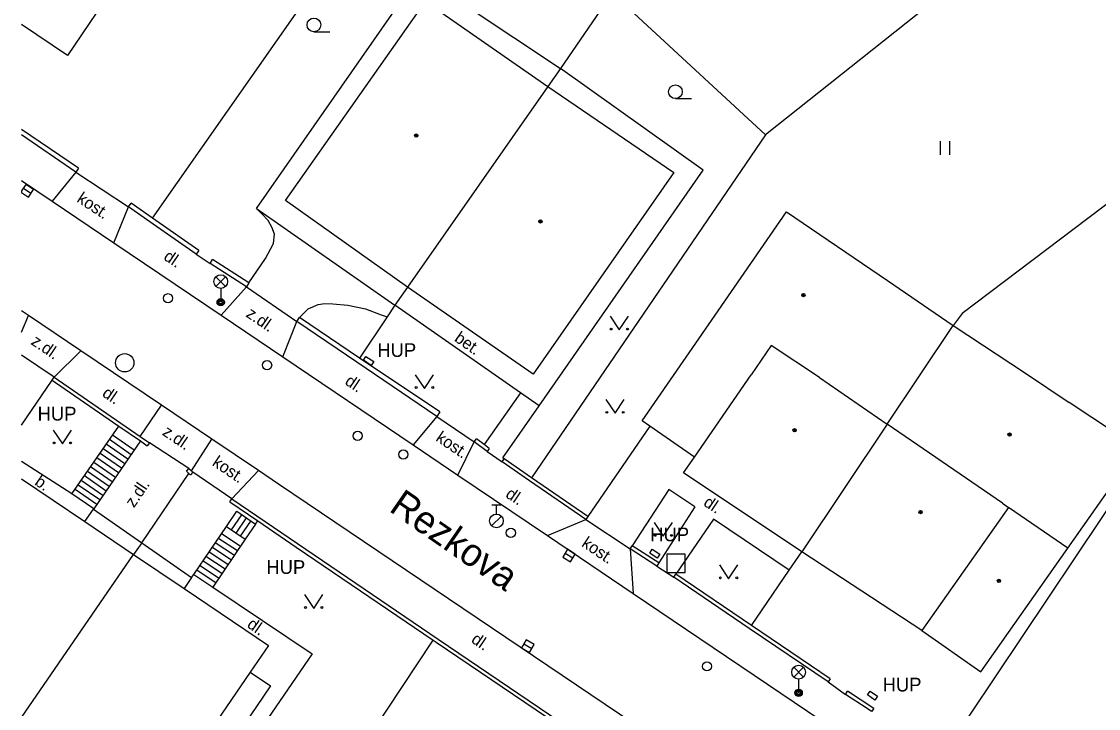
# Model space of a CAD drawing. Extents: x -600391 to -599491, y -1160176 to -1159402.
# Drawn here: x -600391 to -600332.3, y -1160041.1 to -1160003.6 of the extents above; entities that cross this region are included whole.
import ezdxf

# ---------------------------------------------------------------- set-up
doc = ezdxf.new("R2010")
doc.units = 0
for name, color, linetype in [('Level 10', 7, 'Continuous'), ('Level 11', 7, 'Continuous'), ('Level 24', 7, 'Continuous'), ('Level 26', 7, 'Continuous'), ('Level 27', 7, 'Continuous'), ('Level 28', 7, 'Continuous'), ('Level 33', 7, 'Continuous'), ('Level 36', 7, 'Continuous'), ('Level 39', 7, 'Continuous'), ('Level 40', 7, 'Continuous'), ('Level 41', 7, 'Continuous'), ('Level 49', 7, 'Continuous'), ('Level 5', 7, 'Continuous'), ('Level 7', 7, 'Continuous'), ('Level 8', 7, 'Continuous'), ('Vrstva 27', 7, 'Continuous')]:
    doc.layers.add(name, color=color, linetype=linetype)

msp = doc.modelspace()

# ---------------------------------------------------------------- linework, layer by layer
at = {"layer": 'Level 10'}
for points in [[(-600391.008, -1160012.297), (-600389.33, -1160013.43), (-600385.97, -1160015.7), (-600380.12, -1160019.65), (-600376.77, -1160021.91), (-600369.66, -1160026.71), (-600367.22, -1160028.36), (-600362.33, -1160031.66), (-600357.66, -1160034.81), (-600345.98, -1160042.7), (-600342.95, -1160044.75), (-600341.58, -1160045.67), (-600338.1, -1160048.02), (-600335.29, -1160049.92), (-600325.8, -1160056.33), (-600315.13, -1160063.54), (-600309.38, -1160067.42), (-600304.6, -1160070.65), (-600301.7, -1160072.61), (-600258.67, -1160101.64)], [(-600376.99, -1160028.86), (-600378.09, -1160028.12), (-600380.63, -1160026.4), (-600383.37, -1160024.55), (-600387.77, -1160021.58), (-600390.62, -1160019.66), (-600391.008, -1160019.398)], [(-600286.14, -1160090.13), (-600298.33, -1160081.92), (-600327.82, -1160062.03), (-600331.39, -1160059.62), (-600334.69, -1160057.39), (-600338.31, -1160054.95), (-600376.99, -1160028.86)]]:
    msp.add_lwpolyline(points, dxfattribs=at)
at = {"layer": 'Level 11'}
for p, q in [((-600391.008, -1160020.577), (-600390.62, -1160019.66)), ((-600388.26, -1160029.39), (-600391.008, -1160027.625))]:
    msp.add_line(p, q, dxfattribs=at)
for points in [[(-600378.19, -1160013.82), (-600369.31, -1160001.07)], [(-600369.31, -1160001.07), (-600361.63, -1160006.19)], [(-600353.85, -1160011.73), (-600361.63, -1160006.19)], [(-600388.05, -1160011.84), (-600389.33, -1160013.43)], [(-600362.79, -1160024.58), (-600353.85, -1160011.73)], [(-600385.97, -1160015.7), (-600385.18, -1160013.73)], [(-600378.61, -1160017.88), (-600377.7, -1160016.55), (-600377.27, -1160015.74), (-600377.21, -1160015.23), (-600377.36, -1160014.85), (-600377.56, -1160014.48), (-600377.9, -1160014.12), (-600378.19, -1160013.82)], [(-600378.19, -1160013.82), (-600370.65, -1160019.1)], [(-600378.74, -1160018.09), (-600380.12, -1160019.65)], [(-600375.86, -1160019.77), (-600375.39, -1160019.29), (-600374.84, -1160019.07), (-600374.47, -1160019.01), (-600374.03, -1160019.03), (-600373.22, -1160019.1), (-600372.26, -1160019.3), (-600371.41, -1160019.62), (-600371.08, -1160019.74)], [(-600362.79, -1160024.58), (-600363.81, -1160023.87), (-600370.65, -1160019.1)], [(-600376.77, -1160021.91), (-600376, -1160019.98)], [(-600387.77, -1160021.58), (-600389.23, -1160023.03)], [(-600363.81, -1160023.87), (-600365.79, -1160026.7)], [(-600384.54, -1160026.25), (-600383.37, -1160024.55)], [(-600364.7, -1160027.48), (-600364.77, -1160027.43), (-600362.79, -1160024.58)], [(-600368.37, -1160025.16), (-600369.66, -1160026.71)], [(-600384.52, -1160026.5), (-600387.07, -1160030.21), (-600388.26, -1160029.39), (-600385.71, -1160025.69)], [(-600356.75, -1160025.7), (-600360.13, -1160030.62)], [(-600384.87, -1160027), (-600386.05, -1160026.19)], [(-600385.38, -1160027.74), (-600386.56, -1160026.93)], [(-600385.21, -1160027.5), (-600386.39, -1160026.68)], [(-600385.04, -1160027.25), (-600386.22, -1160026.43)], [(-600381.75, -1160028.13), (-600380.63, -1160026.4)], [(-600367.22, -1160028.36), (-600366.33, -1160026.54)], [(-600385.72, -1160028.24), (-600386.9, -1160027.42)], [(-600385.55, -1160027.99), (-600386.73, -1160027.18)], [(-600386.06, -1160028.73), (-600387.24, -1160027.92)], [(-600385.89, -1160028.49), (-600387.07, -1160027.67)], [(-600378.09, -1160028.12), (-600379.55, -1160029.65)], [(-600386.57, -1160029.47), (-600387.75, -1160028.66)], [(-600386.4, -1160029.23), (-600387.58, -1160028.41)], [(-600386.23, -1160028.98), (-600387.41, -1160028.16)], [(-600386.91, -1160029.97), (-600388.09, -1160029.15)], [(-600386.74, -1160029.72), (-600387.92, -1160028.91)], [(-600355.72, -1160029.15), (-600357.71, -1160032.22)], [(-600354.3, -1160030.1), (-600355.72, -1160029.15)], [(-600379.84, -1160031.17), (-600379.27, -1160030.33)], [(-600379.27, -1160030.33), (-600378.25, -1160031.04)], [(-600354.3, -1160030.1), (-600356.27, -1160033.15)], [(-600387.55, -1160030.9), (-600384.9, -1160032.69)], [(-600379.56, -1160031.35), (-600378.99, -1160030.53)], [(-600379.31, -1160031.52), (-600378.74, -1160030.7)], [(-600379.07, -1160031.69), (-600378.5, -1160030.87)], [(-600378.25, -1160031.04), (-600378.82, -1160031.86)], [(-600378.25, -1160031.04), (-600378.13, -1160030.86)], [(-600362.33, -1160031.66), (-600360.24, -1160030.78)], [(-600353.29, -1160030.77), (-600355.33, -1160033.76)], [(-600349.15, -1160033.54), (-600353.29, -1160030.77)], [(-600381.62, -1160033.78), (-600379.84, -1160031.17)], [(-600380.13, -1160031.53), (-600379.07, -1160032.24)], [(-600379.84, -1160031.17), (-600378.82, -1160031.86)], [(-600378.82, -1160031.86), (-600380.57, -1160034.48)], [(-600380.46, -1160032.03), (-600379.4, -1160032.73)], [(-600380.3, -1160031.78), (-600379.24, -1160032.48)], [(-600384.9, -1160032.69), (-600382.15, -1160034.55)], [(-600380.96, -1160032.78), (-600379.9, -1160033.48)], [(-600380.8, -1160032.53), (-600379.74, -1160033.23)], [(-600380.63, -1160032.28), (-600379.57, -1160032.98)], [(-600357.82, -1160032.39), (-600357.66, -1160034.81)], [(-600351.22, -1160036.56), (-600349.15, -1160033.54), (-600348.47, -1160032.55)], [(-600381.3, -1160033.27), (-600380.24, -1160033.98)], [(-600381.13, -1160033.02), (-600380.07, -1160033.73)], [(-600381.74, -1160033.95), (-600381.62, -1160033.78)], [(-600381.62, -1160033.78), (-600380.57, -1160034.48)], [(-600381.46, -1160033.52), (-600380.4, -1160034.23)], [(-600380.57, -1160034.48), (-600375.17, -1160038.1), (-600382.21, -1160048.4), (-600382.91, -1160047.96), (-600385.26, -1160051.34)], [(-600378.54, -1160039.1), (-600383.44, -1160046.26)]]:
    msp.add_lwpolyline(points, dxfattribs=at)
at = {"layer": 'Level 24'}
for points in [[(-600372.23, -1160021.89), (-600371.81, -1160022.17), (-600371.95, -1160022.38), (-600372.37, -1160022.1), (-600372.23, -1160021.89)], [(-600356.62, -1160032.4), (-600356.21, -1160032.68), (-600356.35, -1160032.89), (-600356.76, -1160032.61), (-600356.62, -1160032.4)], [(-600344.75, -1160040.15), (-600344.34, -1160040.42), (-600344.48, -1160040.63), (-600344.89, -1160040.35), (-600344.75, -1160040.15)]]:
    msp.add_lwpolyline(points, dxfattribs=at)
at = {"layer": 'Level 26'}
msp.add_lwpolyline([(-600355.83, -1160033.67), (-600354.83, -1160033.67), (-600354.83, -1160032.67), (-600355.83, -1160032.67)], close=True, dxfattribs=at)
at = {"layer": 'Level 27'}
for p, q in [((-600390.907, -1160012.72), (-600390.493, -1160013)), ((-600361.372, -1160032.618), (-600360.948, -1160032.882)), ((-600363.616, -1160037.564), (-600363.184, -1160037.816))]:
    msp.add_line(p, q, dxfattribs=at)
for points in [[(-600361.504, -1160032.83), (-600361.08, -1160033.094), (-600360.816, -1160032.67), (-600361.24, -1160032.406)], [(-600363.742, -1160037.78), (-600363.31, -1160038.032), (-600363.058, -1160037.6), (-600363.49, -1160037.348)]]:
    msp.add_lwpolyline(points, close=True, dxfattribs=at)
msp.add_circle((-600385.38, -1160022.24), 0.5, dxfattribs=at)
at = {"layer": 'Level 28'}
for p, q in [((-600365.37, -1160029.985), (-600364.87, -1160029.985)), ((-600365.12, -1160030.485), (-600365.12, -1160029.985)), ((-600365.378, -1160031.132), (-600364.848, -1160030.602))]:
    msp.add_line(p, q, dxfattribs=at)
for centre, radius in [((-600383.02, -1160018.72), 0.25), ((-600377.62, -1160022.37), 0.25), ((-600372.68, -1160026.22), 0.25), ((-600370.19, -1160027.24), 0.25), ((-600365.12, -1160030.86), 0.375), ((-600364.33, -1160031.51), 0.25), ((-600353.64, -1160038.79), 0.25)]:
    msp.add_circle(centre, radius, dxfattribs=at)
at = {"layer": 'Level 33'}
for p, q in [((-600380.415, -1160018.08), (-600379.885, -1160017.55)), ((-600380.415, -1160017.55), (-600379.885, -1160018.08)), ((-600380.15, -1160018.19), (-600380.15, -1160018.94)), ((-600348.905, -1160039.37), (-600348.375, -1160038.84)), ((-600348.905, -1160038.84), (-600348.375, -1160039.37)), ((-600348.64, -1160039.48), (-600348.64, -1160040.23))]:
    msp.add_line(p, q, dxfattribs=at)
for centre, radius in [((-600380.15, -1160017.815), 0.375), ((-600380.15, -1160018.94), 0.2), ((-600380.15, -1160018.94), 0.145), ((-600380.15, -1160018.94), 0.0876), ((-600348.64, -1160039.105), 0.375), ((-600348.64, -1160040.23), 0.2), ((-600348.64, -1160040.23), 0.145), ((-600348.64, -1160040.23), 0.0876)]:
    msp.add_circle(centre, radius, dxfattribs=at)
at = {"layer": 'Level 36'}
for p, q in [((-600375.07, -1160004.195), (-600374.195, -1160004.195)), ((-600355.36, -1160007.835), (-600354.485, -1160007.835)), ((-600340.904, -1160010.903), (-600340.904, -1160010.153)), ((-600340.404, -1160010.903), (-600340.404, -1160010.153))]:
    msp.add_line(p, q, dxfattribs=at)
for points in [[(-600358.92, -1160019.7), (-600358.42, -1160020.45), (-600357.92, -1160019.7)], [(-600369.54, -1160022.89), (-600369.04, -1160023.64), (-600368.54, -1160022.89)], [(-600359.15, -1160024.24), (-600358.65, -1160024.99), (-600358.15, -1160024.24)], [(-600389.28, -1160025.91), (-600388.78, -1160026.66), (-600388.28, -1160025.91)], [(-600356.52, -1160030.95), (-600356.02, -1160031.7), (-600355.52, -1160030.95)], [(-600352.96, -1160033.26), (-600352.46, -1160034.01), (-600351.96, -1160033.26)], [(-600375.58, -1160034.88), (-600375.08, -1160035.63), (-600374.58, -1160034.88)]]:
    msp.add_lwpolyline(points, dxfattribs=at)
for centre, radius in [((-600375.07, -1160003.82), 0.375), ((-600355.36, -1160007.46), 0.375), ((-600358.87, -1160020.4), 0.05), ((-600357.971, -1160020.4), 0.05), ((-600369.49, -1160023.59), 0.05), ((-600368.591, -1160023.59), 0.05), ((-600359.1, -1160024.94), 0.05), ((-600358.201, -1160024.94), 0.05), ((-600389.23, -1160026.61), 0.05), ((-600388.331, -1160026.61), 0.05), ((-600356.47, -1160031.65), 0.05), ((-600355.571, -1160031.65), 0.05), ((-600352.91, -1160033.96), 0.05), ((-600352.011, -1160033.96), 0.05), ((-600375.53, -1160035.58), 0.05), ((-600374.631, -1160035.58), 0.05)]:
    msp.add_circle(centre, radius, dxfattribs=at)
at = {"layer": 'Level 39'}
for centre, radius in [((-600369.49, -1160009.85), 0.09), ((-600369.49, -1160009.85), 0.0398), ((-600362.72, -1160014.53), 0.09), ((-600362.72, -1160014.53), 0.0398), ((-600348.38, -1160018.55), 0.09), ((-600348.38, -1160018.55), 0.0398), ((-600348.86, -1160025.92), 0.09), ((-600348.86, -1160025.92), 0.0398), ((-600337.14, -1160026.15), 0.09), ((-600337.14, -1160026.15), 0.0398), ((-600341.99, -1160030.38), 0.09), ((-600341.99, -1160030.38), 0.0398), ((-600337.72, -1160034.13), 0.09), ((-600337.72, -1160034.13), 0.0398)]:
    msp.add_circle(centre, radius, dxfattribs=at)
at = {"layer": 'Level 5'}
for p, q in [((-600388.51, -1160005.48), (-600391.008, -1160003.79)), ((-600391.008, -1160028.561), (-600387.55, -1160030.9)), ((-600391.008, -1160041.584), (-600384.9, -1160032.69))]:
    msp.add_line(p, q, dxfattribs=at)
for points in [[(-600381.83, -1159995.61), (-600388.51, -1160005.48)], [(-600376.61, -1160013.4), (-600368.98, -1160002.54)], [(-600368.98, -1160002.54), (-600362.32, -1160007.18)], [(-600362.32, -1160007.18), (-600369.96, -1160018.11)], [(-600362.32, -1160007.18), (-600355.45, -1160011.87)], [(-600355.45, -1160011.87), (-600363.11, -1160022.86)], [(-600369.96, -1160018.11), (-600376.61, -1160013.4)], [(-600354.08, -1160020.93), (-600349.3, -1160014.01)], [(-600349.3, -1160014.01), (-600343.8, -1160017.76)], [(-600363.11, -1160022.86), (-600369.96, -1160018.11)], [(-600343.8, -1160017.76), (-600340.22, -1160020.2)], [(-600343.81, -1160025.58), (-600340.22, -1160020.2)], [(-600340.22, -1160020.2), (-600336.28, -1160022.81)], [(-600357.17, -1160025.41), (-600354.08, -1160020.93)], [(-600350.13, -1160021.3), (-600351.23, -1160022.9)], [(-600347.51, -1160023.04), (-600350.13, -1160021.3)], [(-600336.28, -1160022.81), (-600333.89, -1160024.4)], [(-600354.32, -1160027.38), (-600351.23, -1160022.9)], [(-600347.51, -1160023.04), (-600343.81, -1160025.58)], [(-600330.13, -1160026.89), (-600333.89, -1160024.4)], [(-600354.32, -1160027.38), (-600356.75, -1160025.7), (-600357.17, -1160025.41)], [(-600343.81, -1160025.58), (-600348.47, -1160032.55)], [(-600337.53, -1160029.89), (-600343.81, -1160025.58)], [(-600333.96, -1160032.34), (-600330.13, -1160026.89)], [(-600354.92, -1160028.24), (-600354.32, -1160027.38)], [(-600348.47, -1160032.55), (-600354.92, -1160028.24)], [(-600387.55, -1160030.9), (-600387.08, -1160030.22)], [(-600387.08, -1160030.22), (-600384.45, -1160032.06)], [(-600337.2, -1160030.12), (-600341.92, -1160036.83)], [(-600337.53, -1160029.89), (-600337.2, -1160030.12)], [(-600333.96, -1160032.34), (-600337.2, -1160030.12)], [(-600384.45, -1160032.06), (-600384.9, -1160032.69)], [(-600384.45, -1160032.06), (-600381.74, -1160033.95)], [(-600341.92, -1160036.83), (-600348.47, -1160032.55)], [(-600338.71, -1160039.09), (-600333.96, -1160032.34)], [(-600381.74, -1160033.95), (-600382.15, -1160034.55)], [(-600382.15, -1160034.55), (-600377.55, -1160037.65)], [(-600341.92, -1160036.83), (-600338.71, -1160039.09)], [(-600377.55, -1160037.65), (-600378.54, -1160039.1)], [(-600378.54, -1160039.1), (-600377.44, -1160039.86)], [(-600377.44, -1160039.86), (-600382.29, -1160047.02)]]:
    msp.add_lwpolyline(points, dxfattribs=at)
at = {"layer": 'Level 7'}
for p, q in [((-600387.91, -1160011.63), (-600391.008, -1160009.513)), ((-600391.008, -1160025.638), (-600389.34, -1160023.19)), ((-600391.008, -1160071.055), (-600368.56, -1160037.37))]:
    msp.add_line(p, q, dxfattribs=at)
for points in [[(-600383.87, -1160014.35), (-600368.75, -1159992.77)], [(-600332.82, -1159995.8), (-600350.45, -1160009.81)], [(-600358.81, -1160002.07), (-600361.63, -1160006.19)], [(-600358.81, -1160002.07), (-600350.45, -1160009.81)], [(-600361.63, -1160006.19), (-600362.32, -1160007.18)], [(-600323.64, -1160007.39), (-600339.73, -1160019.56), (-600340.22, -1160020.2)], [(-600387.91, -1160011.63), (-600388.05, -1160011.84), (-600391.008, -1160009.815)], [(-600350.45, -1160009.81), (-600363.2, -1160028.51)], [(-600381.34, -1160016.12), (-600381.48, -1160016.32), (-600384.01, -1160014.55), (-600385.18, -1160013.73), (-600385.04, -1160013.53)], [(-600381.34, -1160016.12), (-600383.87, -1160014.35), (-600385.04, -1160013.53)], [(-600378.61, -1160017.88), (-600378.74, -1160018.09), (-600380.73, -1160016.82), (-600380.6, -1160016.61)], [(-600378.61, -1160017.88), (-600380.6, -1160016.61)], [(-600369.96, -1160018.11), (-600370.65, -1160019.1)], [(-600370.65, -1160019.1), (-600371.08, -1160019.74), (-600372.59, -1160021.99)], [(-600372.73, -1160022.2), (-600376, -1160019.98), (-600375.86, -1160019.77)], [(-600372.59, -1160021.99), (-600375.86, -1160019.77)], [(-600368.2, -1160024.91), (-600368.37, -1160025.16), (-600372.73, -1160022.2)], [(-600368.2, -1160024.91), (-600372.59, -1160021.99)], [(-600389.34, -1160023.19), (-600389.23, -1160023.03), (-600384.54, -1160026.25), (-600384.04, -1160026.6), (-600384.15, -1160026.76)], [(-600389.34, -1160023.19), (-600389.16, -1160023.31)], [(-600389.16, -1160023.31), (-600385.71, -1160025.69), (-600384.52, -1160026.5), (-600384.15, -1160026.76)], [(-600365.51, -1160026.91), (-600365.63, -1160027.07), (-600366.33, -1160026.54), (-600366.21, -1160026.38)], [(-600365.51, -1160026.91), (-600365.79, -1160026.7), (-600366.21, -1160026.38)], [(-600360.13, -1160030.62), (-600360.24, -1160030.78), (-600363.31, -1160028.67), (-600364.81, -1160027.64), (-600364.7, -1160027.48)], [(-600360.13, -1160030.62), (-600363.2, -1160028.51), (-600364.7, -1160027.48)], [(-600382.02, -1160028.15), (-600381.89, -1160028), (-600381.75, -1160028.13), (-600381.67, -1160028.2), (-600381.8, -1160028.35)], [(-600384.45, -1160032.06), (-600381.88, -1160028.27)], [(-600382.02, -1160028.15), (-600381.88, -1160028.27), (-600381.8, -1160028.35)], [(-600330.72, -1160028.59), (-600340.76, -1160043.59)], [(-600379.66, -1160029.82), (-600379.55, -1160029.65), (-600368.3, -1160037.3), (-600352.28, -1160048.16)], [(-600379.66, -1160029.82), (-600378.13, -1160030.86), (-600376.03, -1160032.29)], [(-600356.27, -1160033.15), (-600356.38, -1160033.32), (-600357.82, -1160032.39), (-600357.71, -1160032.22)], [(-600356.27, -1160033.15), (-600357.71, -1160032.22)], [(-600376.03, -1160032.29), (-600368.56, -1160037.37), (-600368.41, -1160037.47), (-600352.11, -1160048.51), (-600351.38, -1160048.89)], [(-600346.93, -1160039.47), (-600347.04, -1160039.64), (-600351.33, -1160036.72), (-600355.44, -1160033.93), (-600355.33, -1160033.76)], [(-600351.22, -1160036.56), (-600355.33, -1160033.76)], [(-600346.93, -1160039.47), (-600351.22, -1160036.56)], [(-600344.55, -1160041.08), (-600344.66, -1160041.25), (-600344.9, -1160041.09), (-600346.08, -1160040.32), (-600345.97, -1160040.15)], [(-600344.55, -1160041.08), (-600345.97, -1160040.15)]]:
    msp.add_lwpolyline(points, dxfattribs=at)
at = {"layer": 'Level 8'}
msp.add_line((-600389.23, -1160023.03), (-600391.008, -1160021.828), dxfattribs=at)
for points in [[(-600388.05, -1160011.84), (-600385.18, -1160013.73)], [(-600381.48, -1160016.32), (-600380.73, -1160016.82)], [(-600378.74, -1160018.09), (-600376, -1160019.98)], [(-600368.37, -1160025.16), (-600366.33, -1160026.54)], [(-600381.89, -1160028), (-600384.04, -1160026.6)], [(-600365.63, -1160027.07), (-600364.81, -1160027.64)], [(-600379.55, -1160029.65), (-600381.67, -1160028.2)], [(-600360.24, -1160030.78), (-600357.82, -1160032.39)], [(-600356.38, -1160033.32), (-600355.44, -1160033.93)], [(-600347.04, -1160039.64), (-600346.08, -1160040.32)]]:
    msp.add_lwpolyline(points, dxfattribs=at)
at = {"layer": 'Vrstva 27'}
msp.add_lwpolyline([(-600391.008, -1160012.869), (-600391.008, -1160012.953), (-600390.633, -1160013.207), (-600390.353, -1160012.793), (-600390.767, -1160012.513)], close=True, dxfattribs=at)

# ---------------------------------------------------------------- texts
at = {"layer": 'Level 40'}
for s, rotation, p in [('kost.', 326.63363, (-600388.04, -1160013.43)), ('dl.', 325.98572, (-600383.31, -1160016.58)), ('z.dl.', 325.40283, (-600378.82, -1160019.69)), ('z.dl.', 325.86549, (-600390.54, -1160021.2)), ('bet.', 325.03207, (-600367.46, -1160021.02)), ('dl.', 325.98572, (-600373.43, -1160023.38)), ('dl.', 325.98572, (-600386.66, -1160024.03)), ('z.dl.', 325.86549, (-600383.38, -1160026.14)), ('kost.', 325.97549, (-600368.47, -1160026.46)), ('kost.', 325.86549, (-600380.66, -1160027.8)), ('b.', 325.03207, (-600390.34, -1160028.85)), ('z.dl.', 55.82745, (-600384.88, -1160030.18)), ('dl.', 325.98572, (-600364.67, -1160029.53)), ('dl.', 326.24848, (-600353.88, -1160029.99)), ('kost.', 325.97549, (-600360.52, -1160032.21)), ('dl.', 325.03207, (-600378.76, -1160036.62)), ('dl.', 325.98572, (-600366.54, -1160037.45))]:
    msp.add_text(s, height=0.65, rotation=rotation, dxfattribs=at).set_placement(p)
at = {"layer": 'Level 41'}
for p in [(-600371.61, -1160021.92), (-600390.13, -1160025.39), (-600356.73, -1160031.97), (-600377.66, -1160033.75), (-600344.06, -1160040.16)]:
    msp.add_text('HUP', height=0.75, dxfattribs=at).set_placement(p)
at = {"layer": 'Level 49'}
msp.add_text('Rezkova', height=1.5, rotation=325.29, dxfattribs=at).set_placement((-600371.03, -1160030.29))

doc.saveas('drawing.dxf')
